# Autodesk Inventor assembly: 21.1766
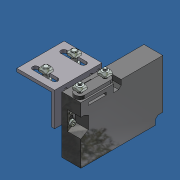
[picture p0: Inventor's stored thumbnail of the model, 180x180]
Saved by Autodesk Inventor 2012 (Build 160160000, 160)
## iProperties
Created: 2007-05
Part Number: 21.1766
Document SubType Name: Assembly
Designer: Andy Moles
Description: SECURITY SWITCH WITH LOCK
Author: Andy Moles
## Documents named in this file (7)
- C:\Andys Backup Data\ANDY'S INVENTOR\INVENTOR LIBRARIES\PARTS LIBRARY\ELECTRICAL INSTALLATION\21.1766 SECURITY SWITCH WITH LOCK.iam
- C:\Andys Backup Data\ANDY'S INVENTOR\INVENTOR LIBRARIES\PARTS LIBRARY\FASTENING ELEMENTS\SCREWS CAP\21.1235 M5X16.ipt
- C:\Andys Backup Data\ANDY'S INVENTOR\INVENTOR LIBRARIES\PARTS LIBRARY\ELECTRICAL INSTALLATION\21.1359 ANGLE BRACKET FOR SECURITY SWITCH.iam
- C:\Andys Backup Data\ANDY'S INVENTOR\INVENTOR LIBRARIES\PARTS LIBRARY\ELECTRICAL INSTALLATION\SUBCOMPONENTS\21.1766 SECURITY SWITCH WITH LOCK BODY NEW.ipt
- C:\Andys Backup Data\ANDY'S INVENTOR\INVENTOR LIBRARIES\PARTS LIBRARY\ELECTRICAL INSTALLATION\SUBCOMPONENTS\21.1110 SECURITY SWITCH AZ 16 ZVR KEY.ipt
- C:\Andys Backup Data\ANDY'S INVENTOR\INVENTOR LIBRARIES\PARTS LIBRARY\FASTENING ELEMENTS\SCREWS COUNTERSUNK\21.1537 M5X18 CSUNK.IPT
- C:\Andys Backup Data\ANDY'S INVENTOR\INVENTOR LIBRARIES\PARTS LIBRARY\FASTENING ELEMENTS\NUTS\21.1320 M5 SQUARE NUT.ipt
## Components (9 placed, 6 different names)
1. 21.1235  M5 x 16:3 — Mate:29, Mate:30
2. 21.1235  M5 x 16:4 — Mate:18, Mate:27, Mate:28
3. 21.1359 ANGLE BRACKET FOR SECURITY SWITCH:1 [sub-assembly] — Mate:18, Mate:23, Flush:6, Mate:29
4. 21.1766 SECURITY SWITCH WITH LOCK BODY NEW:1 — Mate:23, Mate:25, Mate:26, Mate:27, Mate:28, Mate:30
5. 21.1110 SECURITY SWITCH AZ 16 ZVR KEY:1 — Insert:7, Insert:8, Mate:21, Mate:22, Angle:5, Angle:6, Mate:25, Flush:6, Mate:26
6. 21.1537 M5X18 C'SUNK:1 — Insert:8, Mate:19
7. 21.1537 M5X18 C'SUNK:2 — Insert:7, Mate:20
8. 21.1320 M5 SQUARE NUT:1 — Mate:20, Mate:22, Angle:6
9. 21.1320 M5 SQUARE NUT:2 — Mate:19, Mate:21, Angle:5
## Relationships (17: Mate 12, Insert 2, Angle 2, Flush 1)
- Mate:18: 21.1235  M5 x 16:4 ↔ 21.1359 ANGLE BRACKET FOR SECURITY SWITCH:1
- Insert:7: 21.1110 SECURITY SWITCH AZ 16 ZVR KEY:1 ↔ 21.1537 M5X18 C'SUNK:2
- Insert:8: 21.1110 SECURITY SWITCH AZ 16 ZVR KEY:1 ↔ 21.1537 M5X18 C'SUNK:1
- Mate:19: 21.1537 M5X18 C'SUNK:1 ↔ 21.1320 M5 SQUARE NUT:2
- Mate:20: 21.1537 M5X18 C'SUNK:2 ↔ 21.1320 M5 SQUARE NUT:1
- Mate:21: 21.1110 SECURITY SWITCH AZ 16 ZVR KEY:1 ↔ 21.1320 M5 SQUARE NUT:2
- Mate:22: 21.1110 SECURITY SWITCH AZ 16 ZVR KEY:1 ↔ 21.1320 M5 SQUARE NUT:1
- Angle:5: 21.1110 SECURITY SWITCH AZ 16 ZVR KEY:1 ↔ 21.1320 M5 SQUARE NUT:2
- Angle:6: 21.1110 SECURITY SWITCH AZ 16 ZVR KEY:1 ↔ 21.1320 M5 SQUARE NUT:1
- Mate:23: 21.1359 ANGLE BRACKET FOR SECURITY SWITCH:1 ↔ 21.1766 SECURITY SWITCH WITH LOCK BODY NEW:1
- Mate:25: 21.1766 SECURITY SWITCH WITH LOCK BODY NEW:1 ↔ 21.1110 SECURITY SWITCH AZ 16 ZVR KEY:1
- Flush:6: 21.1359 ANGLE BRACKET FOR SECURITY SWITCH:1 ↔ 21.1110 SECURITY SWITCH AZ 16 ZVR KEY:1
- Mate:26: 21.1766 SECURITY SWITCH WITH LOCK BODY NEW:1 ↔ 21.1110 SECURITY SWITCH AZ 16 ZVR KEY:1
- Mate:27: 21.1235  M5 x 16:4 ↔ 21.1766 SECURITY SWITCH WITH LOCK BODY NEW:1
- Mate:28: 21.1235  M5 x 16:4 ↔ 21.1766 SECURITY SWITCH WITH LOCK BODY NEW:1
- Mate:29: 21.1235  M5 x 16:3 ↔ 21.1359 ANGLE BRACKET FOR SECURITY SWITCH:1
- Mate:30: 21.1235  M5 x 16:3 ↔ 21.1766 SECURITY SWITCH WITH LOCK BODY NEW:1
